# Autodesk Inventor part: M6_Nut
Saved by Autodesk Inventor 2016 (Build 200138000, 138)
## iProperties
Created: 2015-11
Part Number: M6_Nut
Material: Generic
Document SubType Name: Modeling
Designer: John
Density: 1 g/cm^3
Appearance: Default
Author: John
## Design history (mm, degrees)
feature "Base1"
body "Solid1"
